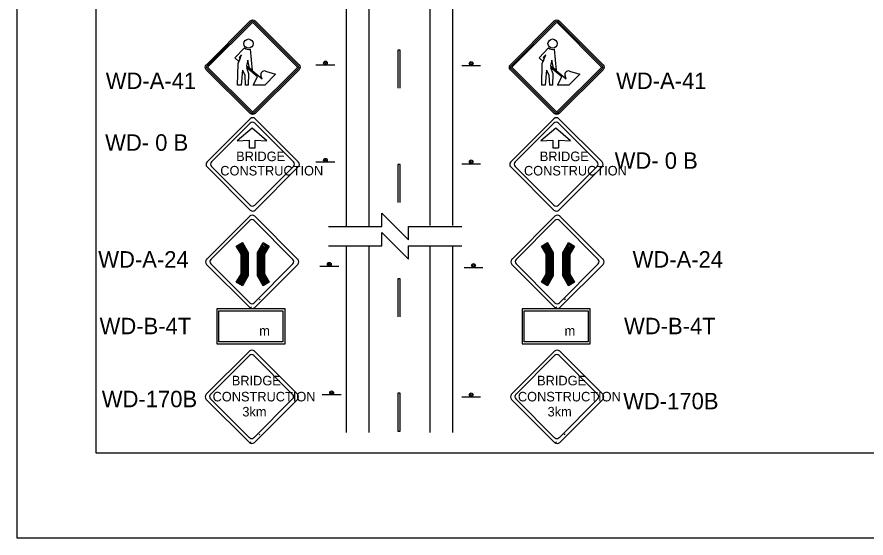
# Model space of a CAD drawing. Extents: x 2179 to 2395, y 134 to 413.
# Drawn here: x 2178.7 to 2286.7, y 133.8 to 199.9 of the extents above; entities that cross this region are included whole.
import ezdxf

# ---------------------------------------------------------------- set-up
doc = ezdxf.new("R2010")
doc.units = 0
for name, color, linetype in [('Level 1', 7, 'Continuous'), ('Level 10', 7, 'Continuous'), ('Level 2', 7, 'Continuous'), ('Level 20', 7, 'Continuous'), ('Level 44', 7, 'Continuous')]:
    doc.layers.add(name, color=color, linetype=linetype)

# ---------------------------------------------------------------- blocks, each defined once
blk = doc.blocks.new('2_95')
at = {"layer": 'Level 1'}
for points in [[(18.2, 120.1), (22.8, 116.1), (17.2, 102.4), (0, 118.7), (41.5, 161.7)], [(18.2, 120.1), (22.8, 116.1), (17.2, 102.4), (0, 118.7), (41.5, 161.7)], [(32.4, 65), (26.3, 0), (11.7, 0), (13.7, 93.4), (17.3, 102.4), (0, 118.7), (41.5, 161.7)], [(65.4, 155.5), (75, 62.6), (62.6, 72.8), (55.6, 107.5), (49.8, 83.3), (117.7, 27.3), (113, 39.4)], [(65.4, 155.5), (75, 62.6), (62.6, 72.8), (55.6, 107.5), (49.8, 83.3), (117.7, 27.3), (113, 39.4)], [(65.4, 155.5), (75, 62.5), (117.7, 27.3), (113, 39.4)], [(132.9, 60.9), (176.6, 47.8), (129.3, 0), (79.5, 0), (98.2, 36), (49.8, 75.6), (59.3, 50.4), (58, 0), (46.2, 0), (44, 43), (32.4, 65), (26.3, 0), (11.7, 0), (13.7, 93.4), (28.7, 130.9), (18.2, 120.1)], [(132.9, 60.9), (176.6, 47.8), (129.3, 0), (79.5, 0), (98.2, 36), (49.8, 75.6), (59.3, 50.4), (58, 0), (46.2, 0), (44, 43), (32.4, 65), (26.3, 0), (11.7, 0), (13.7, 93.4), (28.7, 130.9), (18.2, 120.1)], [(132.9, 60.9), (176.6, 47.8), (129.3, 0), (79.5, 0), (98.2, 36), (49.8, 75.6), (59.3, 50.4), (58, 0), (46.2, 0), (44, 43), (32.4, 65)]]:
    blk.add_lwpolyline(points, dxfattribs=at)
for points in [[(18.2, 120.1), (22.8, 116.1), (28.7, 130.9)], [(62.6, 72.8), (55.6, 107.5), (49.8, 83.3)]]:
    blk.add_lwpolyline(points, close=True, dxfattribs=at)
blk.add_circle((58.9, 179.8), 20.2, dxfattribs=at)
blk.add_circle((58.9, 179.8), 20.2, dxfattribs=at)
blk.add_circle((58.9, 179.8), 20.2, dxfattribs=at)
for centre, radius, start, end in [((58.9, 179.8), 25.1, 226.3135, 284.9576), ((58.9, 179.8), 25.1, 226.3135, 284.9576), ((58.9, 179.8), 25.1, 226.3135, 284.9576), ((128.2, 45.3), 16.3, 73.381, 201.0999), ((128.2, 45.3), 16.3, 73.381, 201.0999), ((128.2, 45.3), 16.3, 73.381, 201.0999)]:
    blk.add_arc(centre, radius, start, end, dxfattribs=at)
blk = doc.blocks.new('WDA41')
at = {"layer": 'Level 1'}
for p, q in [((-6.55, 0.35), (-0.35, 6.54)), ((-6.41, 0.21), (-0.21, 6.4)), ((-6.27, 0.07), (-0.08, 6.27)), ((0.07, 6.27), (6.27, 0.08)), ((0.21, 6.41), (6.41, 0.21)), ((0.35, 6.54), (6.54, 0.35)), ((0.29, 3.83), (0.3, 3.83)), ((-0.35, -6.54), (-6.55, -0.35)), ((-0.21, -6.4), (-6.41, -0.21)), ((-0.07, -6.27), (-6.27, -0.08)), ((6.27, -0.07), (0.08, -6.27)), ((6.41, -0.21), (0.21, -6.4)), ((6.55, -0.35), (0.35, -6.54))]:
    blk.add_line(p, q, dxfattribs=at)
for centre, radius, start, end in [((0, 6.19), 0.495, 45.0349, 135), ((0, 6.19), 0.3, 45.0349, 135), ((0, 6.19), 0.105, 45.0349, 135), ((-6.2, 0), 0.495, 135, 225.0349), ((-6.2, 0), 0.3, 135, 225.0349), ((-6.2, 0), 0.105, 135, 225.0349), ((6.2, 0), 0.105, 315, 45.035), ((6.2, 0), 0.3, 315, 45.035), ((6.2, 0), 0.495, 315, 45.035), ((0, -6.19), 0.495, 225.0348, 315), ((0, -6.19), 0.3, 225.0348, 315), ((0, -6.19), 0.105, 225.0348, 315)]:
    blk.add_arc(centre, radius, start, end, dxfattribs=at)
at = {"layer": 'Level 1', "xscale": 0.032498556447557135, "yscale": -0.032498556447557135, "rotation": 180}
blk.add_blockref('2_95', (2.5, -2.52), dxfattribs=at)

msp = doc.modelspace()

# ---------------------------------------------------------------- linework, layer by layer
at = {"layer": 'Level 1'}
for p, q in [((2227.14, 195.7), (2227.14, 190.86)), ((2227.43, 195.7), (2227.14, 195.7)), ((2227.14, 195.7), (2227.14, 190.86)), ((2227.43, 195.7), (2227.14, 195.7)), ((2227.43, 190.86), (2227.43, 195.7)), ((2227.43, 190.86), (2227.43, 195.7)), ((2227.14, 181.19), (2227.14, 176.35)), ((2227.43, 181.19), (2227.14, 181.19)), ((2227.14, 181.19), (2227.14, 176.35)), ((2227.43, 181.19), (2227.14, 181.19)), ((2227.43, 176.35), (2227.43, 181.19)), ((2227.43, 176.35), (2227.43, 181.19)), ((2227.14, 166.67), (2227.14, 161.83)), ((2227.43, 166.67), (2227.14, 166.67)), ((2227.14, 166.67), (2227.14, 161.83)), ((2227.43, 166.67), (2227.14, 166.67)), ((2227.43, 161.83), (2227.43, 166.67)), ((2227.43, 161.83), (2227.43, 166.67)), ((2227.14, 152.16), (2227.14, 147.32)), ((2227.43, 152.16), (2227.14, 152.16)), ((2227.14, 152.16), (2227.14, 147.32)), ((2227.43, 152.16), (2227.14, 152.16)), ((2227.43, 147.32), (2227.43, 152.16)), ((2227.43, 147.32), (2227.43, 152.16)), ((2227.14, 147.32), (2227.43, 147.32)), ((2227.14, 147.32), (2227.43, 147.32)), ((2188.75, 144.57), (2188.75, 144.57)), ((2178.75, 133.76), (2178.75, 133.76))]:
    msp.add_line(p, q, dxfattribs=at)
for points in [[(2394.75, 412.76), (2178.75, 412.76), (2178.75, 133.76), (2394.75, 133.76)], [(2375.62, 401.95), (2188.75, 401.95), (2188.75, 144.57), (2375.62, 144.57)]]:
    msp.add_lwpolyline(points, close=True, dxfattribs=at)
at = {"layer": 'Level 10'}
for p, q in [((2220.62, 173.33), (2220.62, 223.01)), ((2223.52, 173.38), (2223.52, 223.01)), ((2231.26, 173.43), (2231.26, 223.03)), ((2234.16, 173.43), (2234.16, 223.03)), ((2220.62, 147.16), (2220.62, 170.88)), ((2223.52, 147.16), (2223.52, 170.88)), ((2231.26, 147.16), (2231.26, 170.88)), ((2234.16, 147.16), (2234.16, 170.88))]:
    msp.add_line(p, q, dxfattribs=at)
for points in [[(2204.4, 162.61), (2212.54, 162.61), (2212.54, 158.65), (2204.4, 158.65)], [(2243.19, 162.61), (2251.34, 162.61), (2251.34, 158.65), (2243.19, 158.65)]]:
    msp.add_lwpolyline(points, close=True, dxfattribs=at)
at = {"layer": 'Level 2'}
for p, q in [((2209.65, 164.09), (2209.55, 163.99)), ((2248.45, 164.09), (2248.35, 163.99)), ((2208.54, 163.07), (2208.44, 162.97)), ((2247.34, 163.07), (2247.23, 162.97)), ((2209.61, 146.96), (2209.51, 146.85)), ((2248.41, 146.96), (2248.31, 146.85)), ((2208.5, 145.94), (2208.4, 145.84)), ((2247.3, 145.94), (2247.19, 145.84))]:
    msp.add_line(p, q, dxfattribs=at)
at = {"layer": 'Level 20'}
for points in [[(2218.34, 173.31), (2225.11, 173.31), (2225.11, 175), (2226.8, 173.31), (2228.49, 171.62), (2228.49, 173.31), (2235.27, 173.31)], [(2218.34, 173.31), (2225.11, 173.31), (2225.11, 175), (2226.8, 173.31), (2228.49, 171.62), (2228.49, 173.31), (2235.27, 173.31)], [(2218.34, 170.87), (2225.11, 170.87), (2225.11, 172.57), (2226.8, 170.87), (2228.49, 169.18), (2228.49, 170.87), (2235.27, 170.87)]]:
    msp.add_lwpolyline(points, dxfattribs=at)
at = {"layer": 'Level 44'}
for p, q in [((2219.15, 193.8), (2216.75, 193.8)), ((2235.27, 193.75), (2237.66, 193.75)), ((2208.38, 186.99), (2202.91, 181.52)), ((2214.5, 181.52), (2209.03, 186.99)), ((2246.98, 186.99), (2241.5, 181.52)), ((2253.1, 181.52), (2247.63, 186.99)), ((2203.46, 181.52), (2208.38, 186.44)), ((2208.63, 185.79), (2206.74, 184.21)), ((2210.51, 184.21), (2208.63, 185.79)), ((2208.97, 186.44), (2213.89, 181.52)), ((2242.05, 181.52), (2246.98, 186.44)), ((2247.22, 185.79), (2245.34, 184.21)), ((2249.1, 184.21), (2247.22, 185.79)), ((2247.56, 186.44), (2252.49, 181.52)), ((2206.74, 184.21), (2208.25, 184.29)), ((2208.25, 184.29), (2208.25, 183.28)), ((2209, 183.28), (2209, 184.29)), ((2209, 184.29), (2210.51, 184.21)), ((2245.34, 184.21), (2246.84, 184.29)), ((2246.84, 184.29), (2246.84, 183.28)), ((2247.6, 183.28), (2247.6, 184.29)), ((2247.6, 184.29), (2249.1, 184.21)), ((2208.25, 183.28), (2209, 183.28)), ((2246.84, 183.28), (2247.59, 183.28)), ((2219.15, 181.46), (2216.75, 181.46)), ((2202.91, 180.87), (2208.38, 175.4)), ((2202.91, 180.87), (2202.91, 180.87)), ((2208.38, 176.01), (2203.46, 180.93)), ((2213.89, 180.93), (2208.97, 176.01)), ((2209.03, 175.4), (2214.5, 180.87)), ((2235.27, 181.26), (2237.66, 181.26)), ((2241.5, 180.87), (2246.98, 175.4)), ((2241.51, 180.87), (2241.5, 180.87)), ((2246.98, 176.01), (2242.05, 180.93)), ((2252.49, 180.93), (2247.56, 176.01)), ((2247.63, 175.4), (2253.1, 180.87)), ((2208.32, 174.61), (2202.84, 169.14)), ((2203.39, 169.14), (2208.32, 174.06)), ((2208.9, 174.06), (2213.82, 169.14)), ((2214.43, 169.14), (2208.96, 174.61)), ((2247.11, 174.61), (2241.64, 169.14)), ((2242.18, 169.14), (2247.11, 174.06)), ((2247.7, 174.06), (2252.62, 169.14)), ((2253.23, 169.14), (2247.76, 174.61)), ((2202.84, 168.49), (2208.32, 163.02)), ((2202.84, 168.49), (2202.84, 168.49)), ((2208.32, 163.63), (2203.39, 168.56)), ((2213.82, 168.56), (2208.9, 163.63)), ((2208.96, 163.02), (2214.43, 168.49)), ((2241.64, 168.49), (2247.11, 163.02)), ((2241.64, 168.49), (2241.64, 168.49)), ((2247.11, 163.63), (2242.18, 168.56)), ((2252.62, 168.56), (2247.7, 163.63)), ((2247.76, 163.02), (2253.23, 168.49)), ((2219.64, 168.24), (2217.24, 168.24)), ((2235.57, 168.1), (2237.96, 168.1)), ((2208.28, 157.48), (2202.8, 152.01)), ((2203.35, 152), (2208.28, 156.93)), ((2208.86, 156.93), (2213.78, 152)), ((2214.39, 152.01), (2208.92, 157.48)), ((2247.07, 157.48), (2241.6, 152.01)), ((2242.14, 152), (2247.07, 156.93)), ((2247.66, 156.93), (2252.58, 152)), ((2253.19, 152.01), (2247.72, 157.48)), ((2202.8, 151.36), (2208.28, 145.88)), ((2202.8, 151.36), (2202.8, 151.36)), ((2208.28, 146.49), (2203.35, 151.42)), ((2213.78, 151.42), (2208.86, 146.49)), ((2208.92, 145.88), (2214.39, 151.36)), ((2219.94, 151.93), (2217.55, 151.93)), ((2235.27, 151.67), (2237.66, 151.67)), ((2241.6, 151.36), (2247.07, 145.88)), ((2241.6, 151.36), (2241.6, 151.36)), ((2247.07, 146.49), (2242.14, 151.42)), ((2252.58, 151.42), (2247.66, 146.49)), ((2247.72, 145.88), (2253.19, 151.36))]:
    msp.add_line(p, q, dxfattribs=at)
for points in [[(2206.62, 166.23), (2207.22, 167.27), (2207.22, 169.79), (2206.62, 170.83), (2207.39, 171.28), (2208.11, 170.03), (2208.11, 167.03), (2207.39, 165.79), (2206.62, 166.23), (2206.76, 166.27), (2207.32, 167.24), (2207.33, 169.81), (2206.76, 170.79), (2207.35, 171.13), (2208, 170.01), (2208, 167.06), (2207.34, 165.94), (2206.76, 166.27), (2206.92, 166.31), (2207.43, 167.21), (2207.44, 169.85), (2206.92, 170.75), (2207.31, 170.97), (2207.89, 169.96), (2207.89, 167.09), (2207.31, 166.09), (2206.92, 166.31), (2207.06, 166.35), (2207.55, 167.18), (2207.54, 169.88), (2207.06, 170.71), (2207.27, 170.82), (2207.78, 169.94), (2207.78, 167.12), (2207.25, 166.23), (2207.06, 166.35), (2207.22, 166.39), (2207.32, 166.34), (2207.22, 166.39), (2207.65, 167.15), (2207.66, 169.91), (2207.22, 170.67), (2207.32, 170.73), (2207.39, 171.28)], [(2210.03, 165.79), (2209.31, 167.03), (2209.31, 170.03), (2210.03, 171.28), (2210.8, 170.83), (2210.2, 169.79), (2210.2, 167.27), (2210.8, 166.23), (2210.03, 165.79), (2210.07, 165.96), (2209.43, 167.06), (2209.44, 169.99), (2210.08, 171.1), (2210.62, 170.78), (2210.07, 169.82), (2210.06, 167.24), (2210.62, 166.28), (2210.07, 165.96), (2210.12, 166.13), (2209.56, 167.1), (2209.56, 169.96), (2210.12, 170.92), (2210.45, 170.73), (2209.94, 169.85), (2209.94, 167.2), (2210.45, 166.32), (2210.12, 166.13), (2210.16, 166.31), (2209.69, 167.13), (2209.69, 169.92), (2210.17, 170.75), (2210.27, 170.68), (2209.81, 169.89), (2209.81, 167.17), (2210.27, 166.37), (2210.16, 166.31), (2210.8, 166.23)], [(2245.41, 166.23), (2246.02, 167.27), (2246.02, 169.79), (2245.41, 170.83), (2246.19, 171.28), (2246.91, 170.03), (2246.91, 167.03), (2246.19, 165.79), (2245.41, 166.23), (2245.56, 166.27), (2246.12, 167.24), (2246.13, 169.81), (2245.56, 170.79), (2246.14, 171.13), (2246.79, 170.01), (2246.79, 167.06), (2246.14, 165.94), (2245.56, 166.27), (2245.71, 166.31), (2246.23, 167.21), (2246.24, 169.85), (2245.71, 170.75), (2246.1, 170.97), (2246.68, 169.96), (2246.68, 167.09), (2246.1, 166.09), (2245.71, 166.31), (2245.86, 166.35), (2246.35, 167.18), (2246.34, 169.88), (2245.86, 170.71), (2246.06, 170.82), (2246.57, 169.94), (2246.57, 167.12), (2246.05, 166.23), (2245.86, 166.35), (2246.02, 166.39), (2246.12, 166.34), (2246.02, 166.39), (2246.45, 167.15), (2246.46, 169.91), (2246.02, 170.67), (2246.12, 170.73), (2246.19, 171.28)], [(2248.83, 165.79), (2248.11, 167.03), (2248.11, 170.03), (2248.83, 171.28), (2249.59, 170.83), (2249, 169.79), (2249, 167.27), (2249.59, 166.23), (2248.83, 165.79), (2248.87, 165.96), (2248.23, 167.06), (2248.23, 169.99), (2248.87, 171.1), (2249.42, 170.78), (2248.87, 169.82), (2248.86, 167.24), (2249.42, 166.28), (2248.87, 165.96), (2248.91, 166.13), (2248.36, 167.1), (2248.36, 169.96), (2248.92, 170.92), (2249.24, 170.73), (2248.74, 169.85), (2248.74, 167.2), (2249.24, 166.32), (2248.91, 166.13), (2248.96, 166.31), (2248.49, 167.13), (2248.49, 169.92), (2248.97, 170.75), (2249.07, 170.68), (2248.61, 169.89), (2248.61, 167.17), (2249.07, 166.37), (2248.96, 166.31), (2249.59, 166.23)]]:
    msp.add_lwpolyline(points, dxfattribs=at)
for points in [[(2212.82, 162.84), (2204.15, 162.84), (2204.15, 158.41), (2212.82, 158.41)], [(2251.61, 162.84), (2242.95, 162.84), (2242.95, 158.41), (2251.61, 158.41)]]:
    msp.add_lwpolyline(points, close=True, dxfattribs=at)
for centre, radius in [((2217.95, 194.07), 0.24), ((2236.47, 194.02), 0.24), ((2217.95, 194.07), 0.12), ((2236.47, 194.02), 0.12), ((2217.95, 181.72), 0.24), ((2217.95, 181.72), 0.12), ((2236.47, 181.53), 0.24), ((2236.47, 181.53), 0.12), ((2218.44, 168.51), 0.24), ((2218.44, 168.51), 0.12), ((2236.77, 168.37), 0.24), ((2236.77, 168.37), 0.12), ((2218.74, 152.2), 0.24), ((2218.74, 152.2), 0.12), ((2236.47, 151.93), 0.24), ((2236.47, 151.93), 0.12)]:
    msp.add_circle(centre, radius, dxfattribs=at)
for centre, radius, start, end in [((2208.71, 186.67), 0.458, 45, 135), ((2247.3, 186.67), 0.458, 45, 135), ((2208.67, 186.15), 0.412, 45, 135), ((2247.27, 186.15), 0.412, 45, 135), ((2203.23, 181.2), 0.458, 135, 225), ((2203.75, 181.22), 0.412, 135, 225), ((2213.6, 181.22), 0.412, 315, 45), ((2214.18, 181.2), 0.458, 315, 45), ((2241.83, 181.2), 0.458, 135, 225), ((2242.35, 181.22), 0.412, 135, 225), ((2252.2, 181.22), 0.412, 315, 45), ((2252.78, 181.2), 0.458, 315, 45), ((2208.67, 176.3), 0.412, 225, 315), ((2247.27, 176.3), 0.412, 225, 315), ((2208.71, 175.72), 0.458, 225, 315), ((2247.3, 175.72), 0.458, 225, 315), ((2208.64, 174.29), 0.458, 45, 135), ((2208.61, 173.77), 0.412, 45, 135), ((2247.44, 174.29), 0.458, 45, 135), ((2247.4, 173.77), 0.412, 45, 135), ((2203.17, 168.82), 0.458, 135, 225), ((2203.68, 168.85), 0.412, 135, 225), ((2213.53, 168.85), 0.412, 315, 45), ((2214.11, 168.82), 0.458, 315, 45), ((2241.96, 168.82), 0.458, 135, 225), ((2242.48, 168.85), 0.412, 135, 225), ((2252.33, 168.85), 0.412, 315, 45), ((2252.91, 168.82), 0.458, 315, 45), ((2208.61, 163.92), 0.412, 225, 315), ((2208.64, 163.35), 0.458, 225, 315), ((2247.4, 163.92), 0.412, 225, 315), ((2247.44, 163.35), 0.458, 225, 315), ((2208.6, 157.16), 0.458, 45, 135), ((2247.4, 157.16), 0.458, 45, 135), ((2208.57, 156.64), 0.412, 45, 135), ((2247.36, 156.64), 0.412, 45, 135), ((2203.13, 151.68), 0.458, 135, 225), ((2203.64, 151.71), 0.412, 135, 225), ((2213.49, 151.71), 0.412, 315, 45), ((2214.07, 151.68), 0.458, 315, 45), ((2241.92, 151.68), 0.458, 135, 225), ((2242.44, 151.71), 0.412, 135, 225), ((2252.29, 151.71), 0.412, 315, 45), ((2252.87, 151.68), 0.458, 315, 45), ((2208.57, 146.79), 0.412, 225, 315), ((2208.6, 146.21), 0.458, 225, 315), ((2247.36, 146.79), 0.412, 225, 315), ((2247.4, 146.21), 0.458, 225, 315)]:
    msp.add_arc(centre, radius, start, end, dxfattribs=at)

# ---------------------------------------------------------------- block references
at = {"layer": 'Level 1', "xscale": 0.9, "yscale": -0.9, "rotation": 180}
for p in [(2208.7, 193.54), (2247.35, 193.54)]:
    msp.add_blockref('WDA41', p, dxfattribs=at)

# ---------------------------------------------------------------- texts
at = {"layer": 'Level 1'}
for p in [(2189.25, 159.63), (2255.9, 159.63)]:
    msp.add_text('WD-B-4T', height=2.09, dxfattribs=at).set_placement(p)
at = {"layer": 'Level 10'}
for s, p in [('WD-A-41', (2190.03, 190.77)), ('WD-A-41', (2254.89, 190.77)), ('WD- 0 B', (2189.95, 182.93)), ('WD- 0 B', (2254.71, 180.64)), ('WD-A-24', (2189.08, 168.09)), ('WD-A-24', (2256.99, 168.09)), ('WD-170B', (2189.53, 150.36)), ('WD-170B', (2255.79, 150.1))]:
    msp.add_text(s, height=2.09, dxfattribs=at).set_placement(p)
at = {"layer": 'Level 44'}
for s, p in [('BRIDGE', (2206.6, 181.61)), ('BRIDGE', (2245.19, 181.61)), ('CONSTRUCTION', (2204.59, 179.79)), ('CONSTRUCTION', (2243.18, 179.79)), ('BRIDGE', (2206.05, 153.14)), ('BRIDGE', (2244.85, 153.14))]:
    msp.add_text(s, height=1.214, rotation=360, dxfattribs=at).set_placement(p)
for s, height, p in [('m', 1.21, (2209.54, 159.47)), ('m', 1.21, (2248.34, 159.47)), ('CONSTRUCTION', 1.2143, (2203.61, 151.1)), ('CONSTRUCTION', 1.2143, (2242.41, 151.1)), ('3km', 1.214, (2207.39, 149.19)), ('3km', 1.214, (2246.18, 149.19))]:
    msp.add_text(s, height=height, dxfattribs=at).set_placement(p)

doc.saveas('drawing.dxf')
